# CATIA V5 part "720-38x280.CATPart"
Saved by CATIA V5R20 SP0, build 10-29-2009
Part number: 720-38x280
Definition: NONE
Nomenclature: 720-38x280
Source: Unknown
Description: 720-38x280
Bounding box of the stored display mesh (mm): x 0 to 280, y -19 to 19, z -19 to 19
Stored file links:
  C:\Users\Utente\Desktop\IO LAVORO\3D X SITO CF\X SITO\720\720-38x280.CATPart
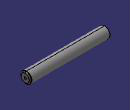
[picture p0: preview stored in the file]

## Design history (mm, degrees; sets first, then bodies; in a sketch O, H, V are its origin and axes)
Body1 "720-38x280" (main body)
  Solid1: solid without history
